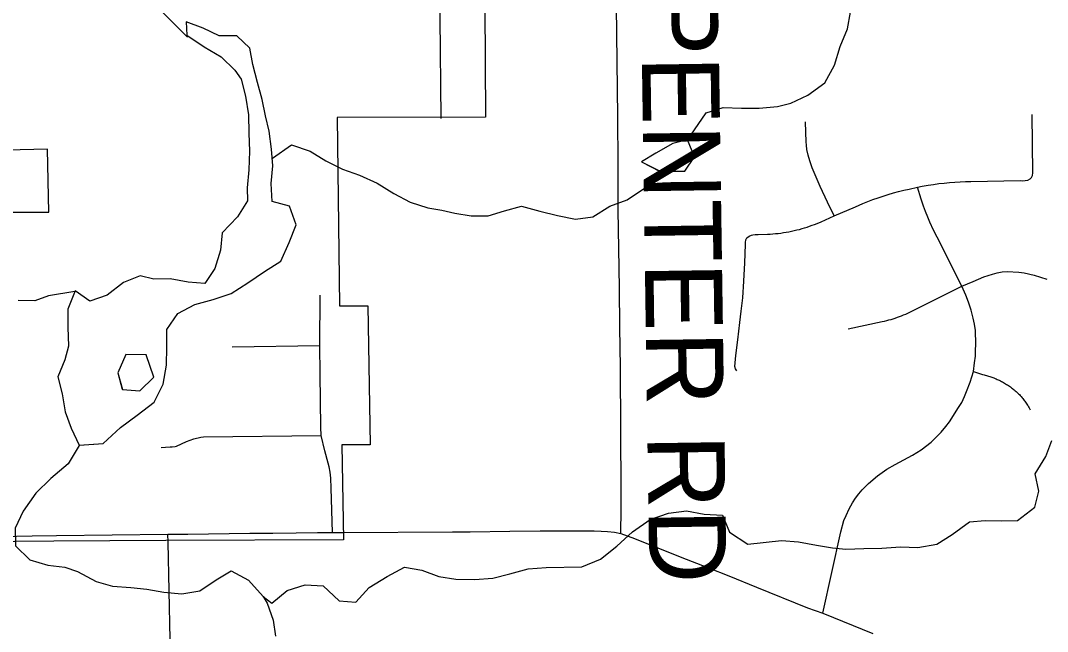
# Model space of a CAD drawing. Extents: x 0 to 34, y 0 to 22.
# Drawn here: x 6.0747 to 6.4527, y 18.3873 to 18.612 of the extents above; entities that cross this region are included whole.
import ezdxf

# ---------------------------------------------------------------- set-up
doc = ezdxf.new("R2010")
doc.units = 0
for name, color, linetype in [('GM_X_City_Street', 7, 'Continuous'), ('GM_X_Corporation', 7, 'Continuous'), ('GM_X_County_Road', 7, 'Continuous'), ('GM_X_Minor_Lake', 7, 'Continuous'), ('GM_X_Minor_River', 7, 'Continuous'), ('GM_X_Township_Road', 7, 'Continuous'), ('GM_X_Township_Road_Text', 7, 'Continuous')]:
    doc.layers.add(name, color=color, linetype=linetype)

msp = doc.modelspace()

# ---------------------------------------------------------------- linework, layer by layer
at = {"layer": 'GM_X_City_Street'}
msp.add_line((6.15256, 18.49196), (6.18483, 18.49242), dxfattribs=at)
for points in [[(6.22955, 18.57599), (6.22917, 18.61299), (6.22893, 18.63385)], [(6.18956, 18.4237), (6.18911, 18.43998), (6.18894, 18.44367), (6.18863, 18.4459), (6.18828, 18.44783), (6.188, 18.44912), (6.18673, 18.45372), (6.18543, 18.4594), (6.18519, 18.46239), (6.18501, 18.48198), (6.18483, 18.49242), (6.18498, 18.51093)], [(6.12648, 18.45492), (6.12813, 18.4551), (6.12975, 18.4552), (6.13058, 18.45524), (6.13157, 18.45534), (6.13216, 18.45547), (6.13585, 18.45719), (6.13851, 18.45815), (6.14109, 18.45877), (6.142, 18.45885), (6.18543, 18.4594)]]:
    msp.add_lwpolyline(points, dxfattribs=at)
at = {"layer": 'GM_X_Corporation'}
for points in [[(6.70502, 19.58201), (6.70762, 19.16786), (6.71181, 18.76657), (6.4441, 18.76539), (6.46064, 18.67204), (6.39724, 18.67173), (6.39724, 18.67218), (6.29309, 18.67122), (6.29363, 18.6175), (6.24566, 18.61703), (6.24591, 18.57643), (6.19122, 18.57632), (6.19207, 18.50705), (6.20259, 18.50704), (6.20346, 18.45598), (6.19295, 18.45598), (6.19355, 18.42096), (6.12817, 18.42074), (6.08699, 18.42046), (6.05815, 18.42026)], [(6.04482, 18.54159), (6.08508, 18.54158), (6.08468, 18.56466), (5.97412, 18.56203)]]:
    msp.add_lwpolyline(points, dxfattribs=at)
at = {"layer": 'GM_X_County_Road'}
for points in [[(6.05669, 18.4221), (6.06218, 18.42217), (6.07317, 18.42231), (6.079, 18.42239), (6.08794, 18.42251), (6.12893, 18.42302), (6.13632, 18.42311), (6.1591, 18.42336), (6.16754, 18.42345), (6.17611, 18.42355), (6.18399, 18.42366), (6.18956, 18.4237), (6.19358, 18.42364)], [(6.19358, 18.42364), (6.23371, 18.4239), (6.24022, 18.42396), (6.25478, 18.42416), (6.26603, 18.42429), (6.28586, 18.42422), (6.2884, 18.42415), (6.29074, 18.42403), (6.29334, 18.42377), (6.29562, 18.42331)], [(6.29562, 18.42331), (6.30075, 18.42142), (6.31746, 18.41473), (6.328, 18.41063), (6.33541, 18.40777), (6.34561, 18.40361), (6.3644, 18.396), (6.37006, 18.39397), (6.38838, 18.38656)]]:
    msp.add_lwpolyline(points, dxfattribs=at)
at = {"layer": 'GM_X_Minor_Lake'}
for points in [[(6.09629, 18.45574), (6.10513, 18.45636), (6.11145, 18.46235), (6.11761, 18.46682), (6.12396, 18.47168), (6.12725, 18.47819), (6.12845, 18.48523), (6.12852, 18.49187), (6.1286, 18.49832), (6.13265, 18.50428), (6.13884, 18.50761), (6.14561, 18.50944), (6.1522, 18.51164), (6.15837, 18.51554), (6.16454, 18.51964), (6.17052, 18.52353), (6.17362, 18.53042), (6.17615, 18.53692), (6.17376, 18.54371), (6.1673, 18.54549), (6.16699, 18.55212), (6.16764, 18.55859), (6.16715, 18.56465), (6.16628, 18.57128), (6.16485, 18.57694), (6.16361, 18.58299), (6.16199, 18.58923), (6.16017, 18.59584), (6.15912, 18.60189), (6.15431, 18.60636), (6.14788, 18.60643), (6.14197, 18.60918), (6.13569, 18.61153), (6.13596, 18.6066), (6.14228, 18.60235), (6.14858, 18.59867), (6.15359, 18.59382)], [(6.09638, 18.45574), (6.10513, 18.45636), (6.11145, 18.46235), (6.11761, 18.46682), (6.12396, 18.47168), (6.12725, 18.47819), (6.12845, 18.48523), (6.12852, 18.49187), (6.1286, 18.49832), (6.13265, 18.50428), (6.13884, 18.50761), (6.14561, 18.50944), (6.1522, 18.51164), (6.15837, 18.51554), (6.16454, 18.51964), (6.17052, 18.52353), (6.17362, 18.53042), (6.17615, 18.53692), (6.17376, 18.54371), (6.1673, 18.54549), (6.16699, 18.55212), (6.16764, 18.55859), (6.16715, 18.56465), (6.16628, 18.57128), (6.16485, 18.57694), (6.16361, 18.58299), (6.16199, 18.58923), (6.16017, 18.59584), (6.15912, 18.60189), (6.15431, 18.60636), (6.14788, 18.60643), (6.14197, 18.60918), (6.13569, 18.61153), (6.13596, 18.6066), (6.14228, 18.60235), (6.14858, 18.59867), (6.15359, 18.59382)], [(6.15359, 18.59382), (6.15592, 18.59045), (6.15754, 18.58421), (6.1586, 18.5774), (6.15872, 18.57057), (6.15903, 18.56394), (6.15877, 18.5571), (6.15813, 18.55045), (6.15822, 18.54571), (6.15454, 18.53976), (6.14897, 18.53397), (6.14832, 18.52751), (6.14617, 18.52083), (6.14249, 18.51526), (6.13642, 18.51573), (6.12978, 18.51694), (6.12373, 18.51683), (6.11879, 18.51807), (6.11259, 18.51569), (6.10662, 18.51103), (6.10023, 18.50883), (6.09487, 18.51253), (6.09215, 18.50584), (6.09208, 18.4992), (6.09239, 18.49219), (6.09096, 18.48723), (6.08843, 18.48092), (6.09005, 18.47469), (6.09111, 18.46807), (6.0933, 18.46203), (6.09629, 18.45574)], [(6.15359, 18.59382), (6.15592, 18.59045), (6.15754, 18.58421), (6.1586, 18.5774), (6.15872, 18.57057), (6.15903, 18.56394), (6.15877, 18.5571), (6.15813, 18.55045), (6.15822, 18.54571), (6.15454, 18.53976), (6.14897, 18.53397), (6.14832, 18.52751), (6.14617, 18.52083), (6.14249, 18.51526), (6.13642, 18.51573), (6.12978, 18.51694), (6.12373, 18.51683), (6.11879, 18.51807), (6.11259, 18.51569), (6.10662, 18.51103), (6.10023, 18.50883), (6.09487, 18.51253), (6.09215, 18.50584), (6.09208, 18.4992), (6.09239, 18.49219), (6.09096, 18.48723), (6.08843, 18.48092), (6.09005, 18.47469), (6.09111, 18.46807), (6.0933, 18.46203), (6.09625, 18.45582)], [(6.32025, 18.5682), (6.31483, 18.56684), (6.30859, 18.56323), (6.30329, 18.56), (6.30994, 18.55667)], [(6.32012, 18.56817), (6.31483, 18.56684), (6.30859, 18.56323), (6.30329, 18.56), (6.3101, 18.55659)], [(6.30973, 18.55667), (6.31918, 18.55659), (6.32277, 18.56191), (6.32027, 18.56814)], [(6.30994, 18.55667), (6.31918, 18.55659), (6.32277, 18.56191), (6.32025, 18.5682)], [(6.12097, 18.48899), (6.11344, 18.48914), (6.11053, 18.48245), (6.1122, 18.47623)], [(6.12109, 18.48899), (6.11344, 18.48914), (6.11053, 18.48245), (6.11215, 18.4764)], [(6.11219, 18.47623), (6.11859, 18.47576), (6.1238, 18.48078), (6.12098, 18.48899)], [(6.1122, 18.47623), (6.11859, 18.47576), (6.1238, 18.48078), (6.12097, 18.48899)]]:
    msp.add_lwpolyline(points, dxfattribs=at)
at = {"layer": 'GM_X_Minor_River'}
for points in [[(6.12703, 18.61496), (6.13622, 18.60595)], [(6.32003, 18.56791), (6.32712, 18.57808), (6.33332, 18.58009), (6.34014, 18.57983), (6.34657, 18.57975), (6.35337, 18.58044), (6.35826, 18.58166), (6.36445, 18.58462), (6.3708, 18.58909), (6.37428, 18.5956), (6.37643, 18.60247), (6.37915, 18.60897), (6.38018, 18.61506)], [(6.1674, 18.56143), (6.1745, 18.5663), (6.18135, 18.56395), (6.18708, 18.56045), (6.19319, 18.55733), (6.19947, 18.55516), (6.20595, 18.55224), (6.21207, 18.54836), (6.21818, 18.54524), (6.22465, 18.54308), (6.22977, 18.54222), (6.23452, 18.54116), (6.24059, 18.54013), (6.24683, 18.54024), (6.25285, 18.54206), (6.25906, 18.54368), (6.2659, 18.54191), (6.27236, 18.54031), (6.27901, 18.53891), (6.28542, 18.53978), (6.2916, 18.54368), (6.29799, 18.54607), (6.30434, 18.55036), (6.30996, 18.55667)], [(6.09475, 18.5123), (6.08498, 18.51076), (6.07992, 18.50894), (6.07387, 18.50899)], [(6.16399, 18.40009), (6.16725, 18.39768), (6.17284, 18.40233), (6.17943, 18.40435), (6.18605, 18.40408), (6.19201, 18.3985), (6.19807, 18.39803), (6.20309, 18.40343), (6.20963, 18.40753), (6.21601, 18.41087), (6.22246, 18.40984), (6.22874, 18.40749), (6.235, 18.40646), (6.24181, 18.40639), (6.24861, 18.40689), (6.25482, 18.40851), (6.2616, 18.41034), (6.26821, 18.41084), (6.28126, 18.41106), (6.28821, 18.41384), (6.29417, 18.41869), (6.29994, 18.42391), (6.30649, 18.42839), (6.31325, 18.43079), (6.31986, 18.43166), (6.32631, 18.43045), (6.33313, 18.43), (6.33569, 18.42378), (6.34239, 18.41935), (6.35485, 18.4207), (6.3611, 18.42024), (6.36774, 18.41903), (6.37362, 18.418), (6.37855, 18.41751), (6.38516, 18.41782), (6.39178, 18.41793), (6.39858, 18.41843), (6.40502, 18.41817), (6.41199, 18.41943), (6.41761, 18.42294), (6.42396, 18.4276), (6.42981, 18.42809), (6.43586, 18.428), (6.44173, 18.42811), (6.44807, 18.43296), (6.44948, 18.43887), (6.44823, 18.4453), (6.45209, 18.45163), (6.45426, 18.45755)], [(6.09626, 18.45562), (6.09221, 18.44892), (6.08587, 18.4435), (6.08029, 18.43809), (6.07568, 18.43156), (6.07276, 18.42524), (6.07288, 18.41879), (6.07808, 18.41357), (6.08473, 18.4116), (6.09098, 18.41095), (6.09574, 18.40933), (6.10261, 18.40566), (6.10851, 18.40386), (6.11532, 18.40341), (6.1212, 18.40276), (6.12746, 18.40173), (6.13409, 18.40108), (6.14069, 18.40215), (6.14667, 18.40624), (6.15229, 18.40956), (6.15859, 18.40607), (6.16399, 18.40009)], [(6.16399, 18.40009), (6.16555, 18.39765), (6.16774, 18.39143), (6.1686, 18.38556)]]:
    msp.add_lwpolyline(points, dxfattribs=at)
at = {"layer": 'GM_X_Township_Road'}
for points in [[(6.29562, 18.42331), (6.29574, 18.43228), (6.29581, 18.43859), (6.29549, 18.48443), (6.29529, 18.49919), (6.29516, 18.51356), (6.29496, 18.52819), (6.29471, 18.54223), (6.29464, 18.55914), (6.29457, 18.57656), (6.29405, 18.61737)], [(6.37418, 18.54023), (6.37173, 18.54519), (6.369, 18.55102), (6.36613, 18.55778), (6.36525, 18.56047), (6.36464, 18.56255), (6.36416, 18.56461), (6.36404, 18.56616), (6.36395, 18.56741), (6.36376, 18.57102), (6.36367, 18.57473)], [(6.44634, 18.55382), (6.44684, 18.55428), (6.44723, 18.55506), (6.44738, 18.55599), (6.44703, 18.57746)], [(6.3429, 18.53267), (6.34373, 18.53304), (6.34426, 18.53319), (6.34517, 18.53327), (6.34623, 18.53334), (6.34968, 18.53341), (6.35067, 18.53347), (6.35166, 18.53354), (6.35265, 18.53363), (6.35363, 18.53373), (6.35461, 18.53386), (6.35559, 18.534), (6.35657, 18.53416), (6.35754, 18.53433), (6.35852, 18.53452), (6.3595, 18.53474), (6.36046, 18.53497), (6.36141, 18.53521), (6.36236, 18.53547), (6.3633, 18.53575), (6.36424, 18.53605), (6.36518, 18.53636), (6.3661, 18.53669), (6.36702, 18.53703), (6.36794, 18.53739), (6.36937, 18.53799), (6.37418, 18.54023), (6.38202, 18.54353), (6.38478, 18.5447), (6.38662, 18.54543), (6.38848, 18.54613), (6.39035, 18.5468), (6.39223, 18.54744), (6.39412, 18.54804), (6.39602, 18.54861), (6.39793, 18.54914), (6.39979, 18.54958), (6.40178, 18.55), (6.40493, 18.55069), (6.40664, 18.55107), (6.40875, 18.55147), (6.41072, 18.55176), (6.41268, 18.55202), (6.41465, 18.55225), (6.41663, 18.55244), (6.41861, 18.5526), (6.42059, 18.55272), (6.42257, 18.55281), (6.42455, 18.55286), (6.44277, 18.55312), (6.44366, 18.55308), (6.44451, 18.55314), (6.44548, 18.55335), (6.44634, 18.55382)], [(6.37006, 18.39397), (6.37668, 18.42397), (6.37779, 18.42814), (6.37858, 18.42996), (6.37969, 18.4324), (6.38089, 18.43464), (6.3821, 18.43633), (6.38324, 18.43793), (6.38446, 18.43939), (6.38678, 18.44175), (6.39011, 18.44457), (6.39363, 18.44693), (6.39668, 18.44865), (6.39988, 18.45036), (6.40308, 18.45212), (6.40627, 18.45411), (6.40988, 18.45694), (6.41172, 18.45871), (6.41354, 18.46059), (6.41525, 18.46268), (6.41659, 18.46444), (6.41877, 18.46768), (6.41974, 18.46924), (6.42113, 18.47152), (6.42213, 18.47366), (6.42294, 18.4755), (6.42423, 18.47898), (6.42548, 18.48291), (6.4259, 18.48606), (6.42618, 18.48851), (6.42627, 18.49069), (6.42636, 18.49291), (6.42618, 18.49796), (6.42581, 18.50037), (6.42539, 18.50254), (6.4246, 18.5055), (6.42363, 18.50838), (6.4227, 18.51102), (6.42124, 18.51428), (6.41206, 18.53229), (6.41081, 18.53491), (6.40947, 18.5378), (6.40863, 18.53972), (6.40786, 18.54173), (6.4071, 18.5437), (6.4062, 18.54637), (6.40493, 18.55069)], [(6.33831, 18.48318), (6.33787, 18.48384), (6.33762, 18.4847), (6.33799, 18.48878), (6.33878, 18.49461), (6.33952, 18.50096), (6.34002, 18.50512), (6.34053, 18.50999), (6.34095, 18.51614), (6.34128, 18.5229), (6.34155, 18.52962), (6.34159, 18.53036), (6.34169, 18.53133), (6.34206, 18.53207), (6.3429, 18.53267)], [(6.42124, 18.51428), (6.42531, 18.51607), (6.42928, 18.51768), (6.43248, 18.51875), (6.43419, 18.51916), (6.43608, 18.51954), (6.43789, 18.51972), (6.44215, 18.51949), (6.44419, 18.51916), (6.44776, 18.51838), (6.45252, 18.51689)], [(6.37941, 18.49863), (6.39192, 18.50129), (6.39273, 18.50147), (6.39353, 18.50166), (6.39433, 18.50187), (6.39512, 18.50209), (6.39591, 18.50233), (6.3967, 18.50258), (6.39748, 18.50284), (6.39825, 18.50311), (6.39901, 18.5034), (6.39977, 18.50371), (6.40052, 18.50402), (6.40127, 18.50435), (6.40201, 18.5047), (6.40322, 18.50529), (6.42124, 18.51428)], [(6.42548, 18.48291), (6.42877, 18.48185), (6.42944, 18.48167), (6.42984, 18.48157), (6.43024, 18.48146), (6.43065, 18.48135), (6.43104, 18.48123), (6.43144, 18.4811), (6.43184, 18.48097), (6.43223, 18.48083), (6.43263, 18.48068), (6.43302, 18.48053), (6.43342, 18.48036), (6.43381, 18.4802), (6.4342, 18.48002), (6.43459, 18.47984), (6.43498, 18.47966), (6.43537, 18.47946), (6.43575, 18.47926), (6.43614, 18.47906), (6.43652, 18.47885), (6.43689, 18.47863), (6.43727, 18.4784), (6.43764, 18.47817), (6.43801, 18.47794), (6.43837, 18.4777), (6.43873, 18.47745), (6.43909, 18.4772), (6.43944, 18.47694), (6.43979, 18.47668), (6.44013, 18.47641), (6.44047, 18.47613), (6.4408, 18.47585), (6.44113, 18.47557), (6.44145, 18.47528), (6.44177, 18.47498), (6.44208, 18.47468), (6.44238, 18.47438), (6.44268, 18.47407), (6.44297, 18.47375), (6.44342, 18.47324), (6.44368, 18.47292), (6.44394, 18.4726), (6.44419, 18.47227), (6.44444, 18.47194), (6.44468, 18.4716), (6.44492, 18.47126), (6.44515, 18.47092), (6.44537, 18.47057), (6.44558, 18.47022), (6.44579, 18.46986), (6.446, 18.4695), (6.44639, 18.46877)], [(6.13375, 18.16831), (6.13366, 18.16933), (6.13345, 18.18016), (6.13319, 18.18965), (6.13308, 18.19525), (6.13275, 18.22026), (6.13208, 18.27046), (6.13198, 18.27779), (6.13179, 18.28681), (6.13147, 18.3024), (6.13114, 18.318), (6.13072, 18.33803), (6.13023, 18.36102), (6.12991, 18.37658), (6.12975, 18.38433), (6.129, 18.42009), (6.12893, 18.42302)]]:
    msp.add_lwpolyline(points, dxfattribs=at)

# ---------------------------------------------------------------- texts
at = {"layer": 'GM_X_Township_Road_Text'}
msp.add_text('CARPENTER RD', height=0.0284091, rotation=270.8276, dxfattribs=at).set_placement((6.30188, 18.70444))

doc.saveas('drawing.dxf')
